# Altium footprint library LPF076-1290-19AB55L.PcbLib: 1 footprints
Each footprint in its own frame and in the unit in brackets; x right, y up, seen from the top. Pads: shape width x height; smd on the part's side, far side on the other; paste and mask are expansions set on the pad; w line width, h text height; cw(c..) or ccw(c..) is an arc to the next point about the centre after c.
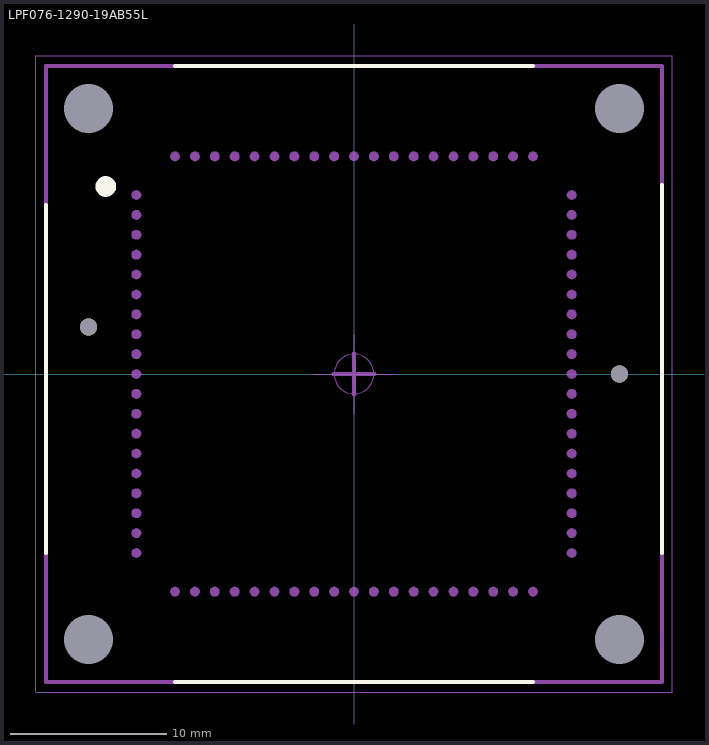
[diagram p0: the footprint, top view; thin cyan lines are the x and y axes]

## LPF076-1290-19AB55L [mm] "CC6UL Socket"
height 0.684
pads (6):
  round 0 / inner round 0 / far side round 6 hole 3.15 unplated: MH-1(-16.95,16.95) MH-2(-16.95,-16.95) MH-3(16.95,-16.95) MH-4(16.95,16.95)
  round 1.1 hole 1.1 unplated mask+0.1: MH-5(-16.95,3) MH-6(16.95,0)
Top Overlay:
  circle w0.65: c-15.85,11.975 r0.335
  lines w0.254: -19.685,-11.43 -19.685,10.795 ; -11.43,-19.685 11.43,-19.685 ; -11.43,19.685 11.43,19.685 ; 19.685,-11.43 19.685,12.065
Assembly Top:
  drawing of 82 lines, arcs and shapes, not listed
  text ".Designator" at -4,2 h2
Courtyard Top:
  circle w0.05: c0,0 r1.27
  lines w0.05: -2.54,0 2.54,0 ; 0,-2.54 0,2.54 ; -20.32,-20.32 -20.32,20.32 20.32,20.32 20.32,-20.32 -20.32,-20.32
3D body: height 26.52, standoff -4.18, extent -20,-19.979 19.958,19.979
